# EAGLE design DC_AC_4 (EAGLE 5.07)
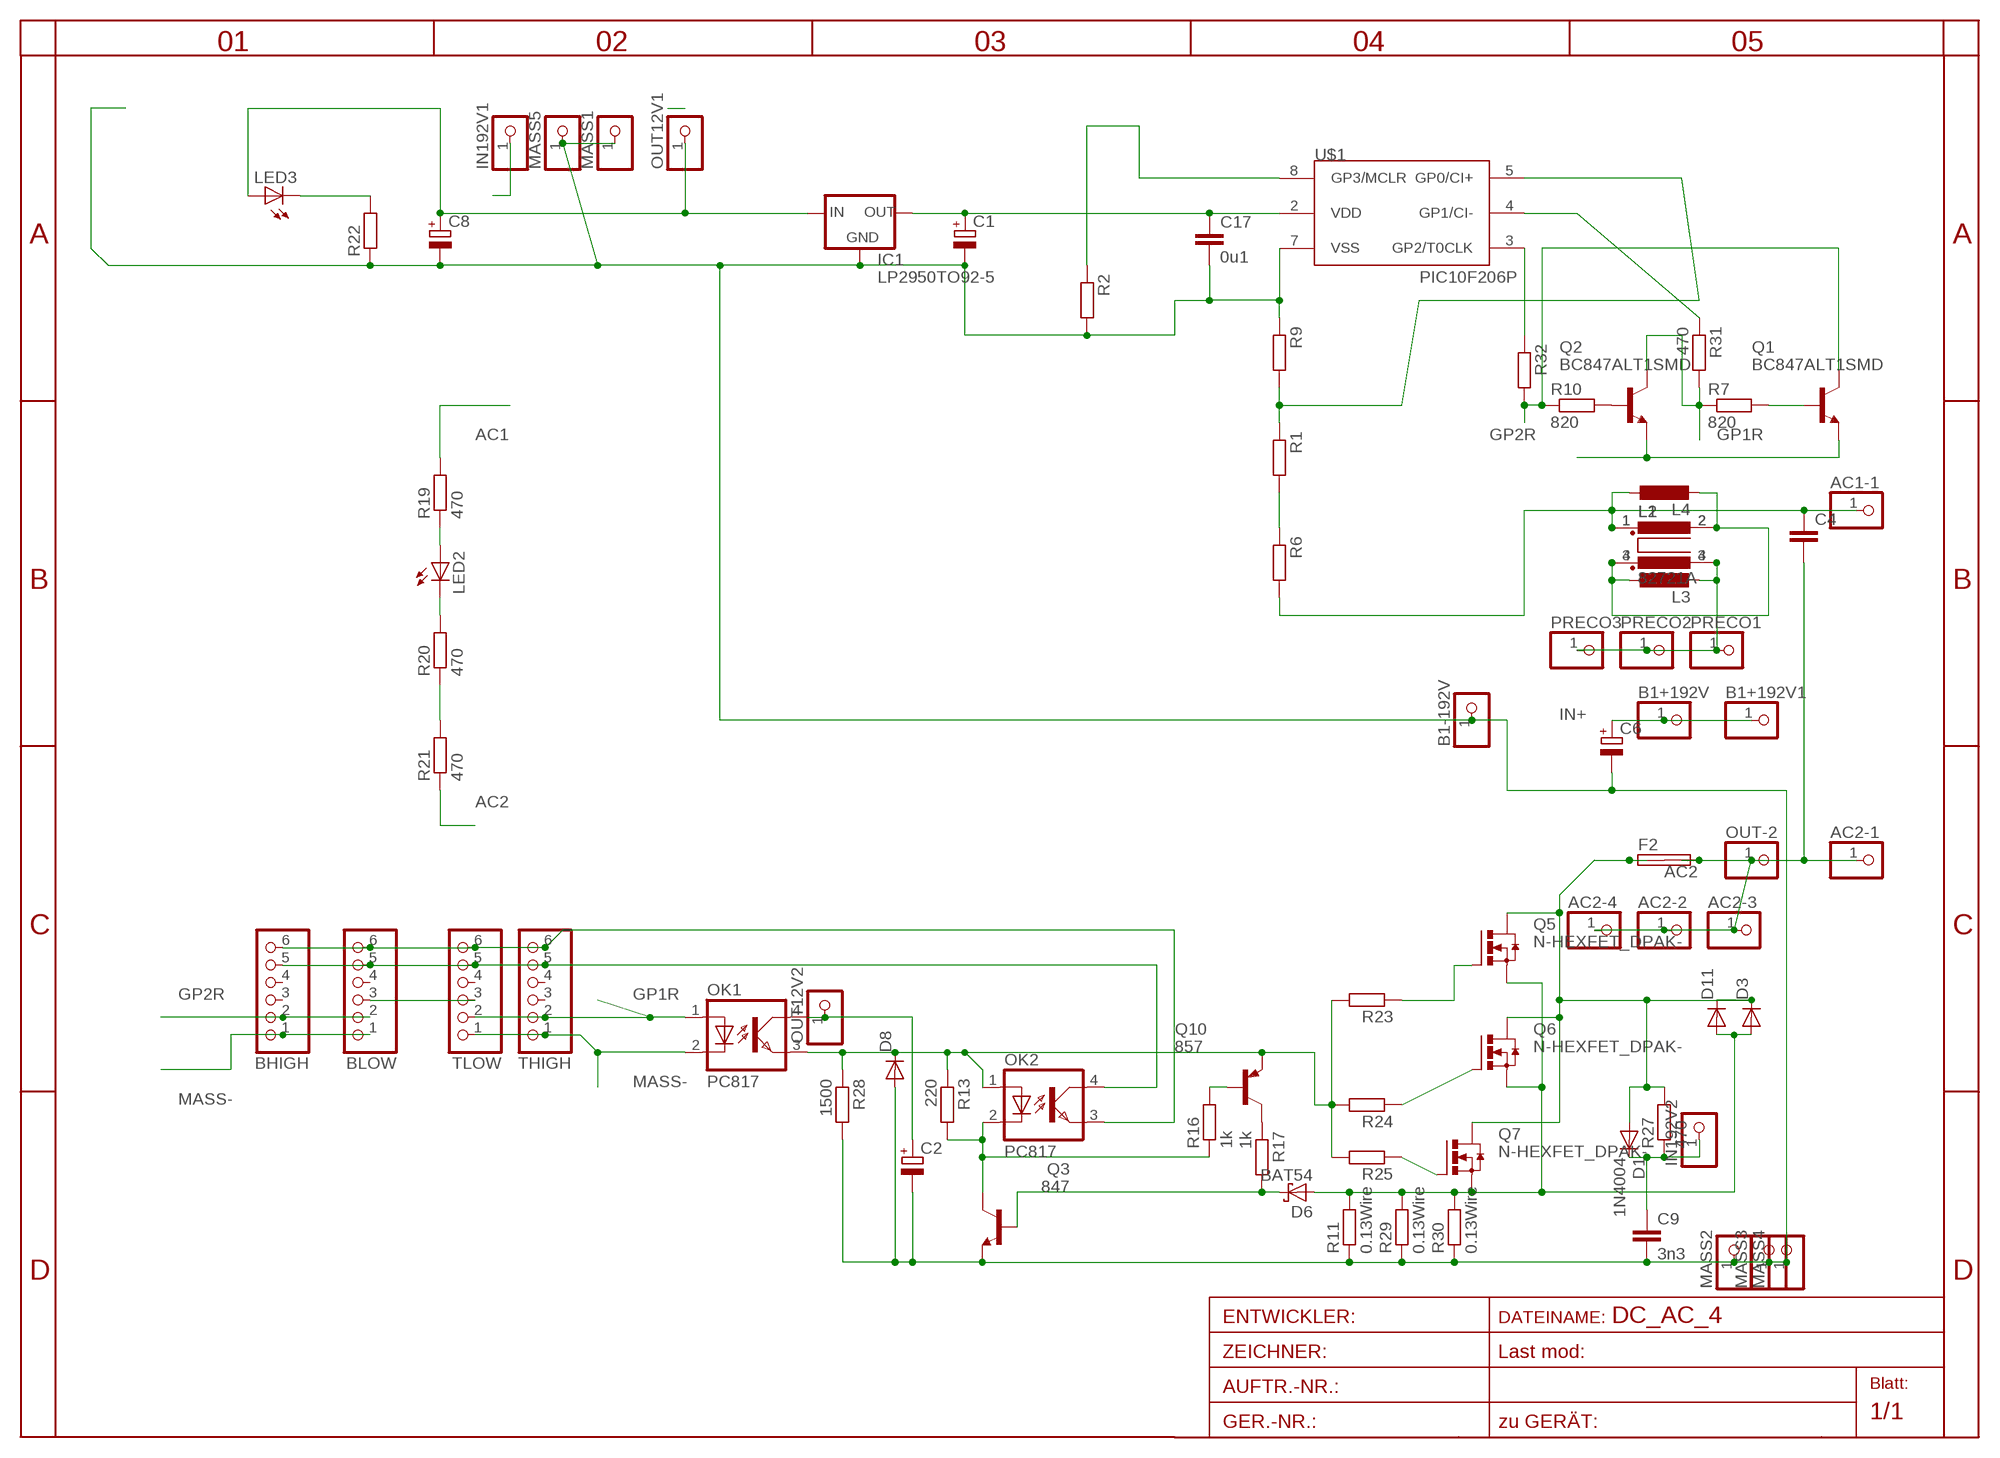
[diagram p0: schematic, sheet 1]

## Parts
AC1-1  PINHD-1X14.5MM  [1X4MM5]
AC2-1  PINHD-1X14.5MM  [1X4MM5]
AC2-2  PINHD-1X12MM3  [1X2MM3]
AC2-3  PINHD-1X12MM3  [1X2MM3]
AC2-4  PINHD-1X12MM3  [1X2MM3]
B1+192V  PINHD-1X12MM3  [1X2MM3]
B1+192V1  PINHD-1X12MM3  [1X2MM3]
B1-192V  PINHD-1X12MM3  [1X2MM3]
BHIGH  PINHD-1X6  [1X06BOX]
BLOW  PINHD-1X6  [1X06BOX]
C1  CPOL-EUE5-6  [E5-6]
C2  CPOL-EUE2.5-5  [E2,5-5]
C4  C-EU225-108X268  [C225-108X268]
C6  CPOL-EUE10-20  [EB20D]
C8  CPOL-EUE5-5  [E5-5]
C9  3n3  C-EU050-025X075  [C050-025X075]
C17  0u1  C-EUC1206  [C1206]
D1  1N4004  [DO41-10]
D3  DIODE-SMC  [SMC]
D6  BAT54  [SOT23]
D8  DIODE-MINIMELF  [MINIMELF]
D11  DIODE-SMC  [SMC]
F2  SHK20L7MM5  [7MM5]
IC1  LP2950TO92-5  [T092-5]
IN192V1  PINHD-1X11MM6  [1X1MM8]
IN192V2  PINHD-1X11MM0  [1X1MM0]
L1  R1405VB1  [B1]
L2  82721A  [82721A]
L3  L-EU2200-15.24  [2200-15.24]
L4  L-EU2200-15.24  [2200-15.24]
LED2  LED3MM  [LED3MM]
LED3  LEDCHIPLED_1206  [CHIPLED_1206]
MASS1  PINHD-1X11MM6  [1X1MM8]
MASS2  PINHD-1X11MM0  [1X1MM0]
MASS3  PINHD-1X11MM6  [1X1MM8]
MASS4  PINHD-1X11MM6  [1X1MM8]
MASS5  PINHD-1X11MM6  [1X1MM8]
OK1  PC817  [DIL04]
OK2  PC817  [DIL04]
OUT12V1  PINHD-1X11MM6  [1X1MM8]
OUT12V2  PINHD-1X11MM0  [1X1MM0]
OUT-2  PINHD-1X12MM3  [1X2MM3]
PRECO1  PINHD-1X12MM3  [1X2MM3]
PRECO2  PINHD-1X12MM3  [1X2MM3]
PRECO3  PINHD-1X12MM3  [1X2MM3]
Q1  BC847ALT1SMD  [SOT23]
Q2  BC847ALT1SMD  [SOT23]
Q3  847  BC846ALT1SMD  [SOT23]
Q5  N-HEXFET_DPAK-  [TO252]
Q6  N-HEXFET_DPAK-  [TO252]
Q7  N-HEXFET_DPAK-  [TO252]
Q10  857  BC857ALT1SMD  [SOT23-BEC]
R1  R-EU_0207/60  [0207/60]
R2  R-EU_R1206  [R1206]
R6  R-EU_0207/10  [0207/10]
R7  820  R-EU_R1206  [R1206]
R9  R-EU_R0805  [R0805]
R10  820  R-EU_R1206  [R1206]
R11  0.13Wire  R-EU_0204/5  [0204/5]
R13  220  R-EU_R1206  [R1206]
R16  1k  R-EU_R0805  [R0805]
R17  1k  R-EU_R0805  [R0805]
R19  470  R-EU_0204/5  [0204/5]
R20  470  R-EU_0204/2V  [0204V]
R21  470  R-EU_0204/5  [0204/5]
R22  R-EU_R1206  [R1206]
R23  R-EU_0207/15  [0207/15]
R24  R-EU_0207/10  [0207/10]
R25  R-EU_0207/12  [0207/12]
R27  470  R-EU_0207/10  [0207/10]
R28  1500  R-EU_R1206  [R1206]
R29  0.13Wire  R-EU_0204/5  [0204/5]
R30  0.13Wire  R-EU_0204/5  [0204/5]
R31  470  R-EU_R1206  [R1206]
R32  R-EU_R1206  [R1206]
THIGH  PINHD-1X6  [1X06BOX]
TLOW  PINHD-1X6  [1X06BOX]
U$1  PIC10F206P  [DIL8]

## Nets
AC1: AC1-1.1 C4.1 L1.1 L2.1 L4.1 R6.2 R19.2
AC2: AC2-1.1 AC2-2.1 AC2-3.1 AC2-4.1 C4.2 F2.2A F2.2B OUT-2.1 R21.1
BATT+: C8.+ IC1.3(IN) LED3.A OUT12V1.1
D1: D1.A D3.C D11.C F2.1A F2.1B Q5.3(D) Q6.3(D) Q7.3(D) R27.2
GP1R: OK1.1(A) Q2.3(C) R7.1 R31.2 THIGH.2 TLOW.2
GP2R: BHIGH.2 BLOW.2 Q1.3(C) R10.1 R32.2
GP3: BHIGH.6 BLOW.6 OK2.3(EMIT) R2.1 THIGH.6 TLOW.6 U$1.8(GP3/MCLR)
IN+: B1+192V1.1 B1+192V.1 C6.+ IN192V1.1
INN: L1.2 L1.3 L2.2 L2.4 L3.1 L4.2
MASS-: B1-192V.1 BHIGH.1 BLOW.1 C1.- C2.- C6.- C8.- C9.2 C17.2 D8.A IC1.2(GND) MASS1.1 MASS2.1 MASS3.1 MASS4.1 MASS5.1 OK1.2(C) Q1.2(E) Q2.2(E) Q3.2(E) R2.2 R9.1 R11.1 R22.1 R28.2 R29.1 R30.1 THIGH.1 TLOW.1 U$1.7(VSS)
N$1: R1.1 R9.2 U$1.5(GP0/CI+)
N$2: C2.+ OK1.4(COL) OUT12V2.1
N$3: R1.2 R6.1
N$4: Q2.1(B) R10.2
N$5: BLOW.3 TLOW.3
N$6: LED2.A R19.1
N$7: Q1.1(B) R7.2
N$9: LED2.K(C) R20.2
N$11: D6.3(C) Q3.1(B) R17.2
N$12: OK2.2(C) Q3.3(C) R13.2 R16.1
N$13: R20.1 R21.2
N$15: LED3.C R22.2
N$16: Q10.B R16.2
N$17: Q10.C R17.1
N$20: C9.1 D1.C IN192V2.1 R27.1
N$25: Q7.1(G) R25.1
N$26: Q6.1(G) R24.1
N$27: Q5.1(G) R23.1
N$39: R31.1 U$1.4(GP1/CI-)
N$43: R32.1 U$1.3(GP2/T0CLK)
PP1: D8.C OK1.3(EMIT) OK2.1(A) Q10.E R13.1 R23.2 R24.2 R25.2 R28.1
PRECOIL: L1.4 L2.3 L3.2 PRECO1.1 PRECO2.1 PRECO3.1
SRC1: D3.A D6.1(A) D11.A Q5.2(S) Q6.2(S) Q7.2(S) R11.2 R29.2 R30.2
VDD: BHIGH.5 BLOW.5 C1.+ C17.1 IC1.1(OUT) OK2.4(COL) THIGH.5 TLOW.5 U$1.2(VDD)
Unconnected: BHIGH.3 BHIGH.4 BLOW.4 THIGH.3 THIGH.4 TLOW.4

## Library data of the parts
AC1-1 AC2-1-AC2-4 B1+192V B1+192V1 B1-192V IN192V1 IN192V2 MASS1-MASS5 OUT12V1 OUT12V2 OUT-2 PRECO1-PRECO3 = pinhead:PINHD-1X1: PIN HEADER
BHIGH BLOW THIGH TLOW = pinhead:PINHD-1X6: PIN HEADER
C1 C2 C8 = rcl-2:CPOL-EU: POLARIZED CAPACITOR, European symbol
C4 = rcl:C-EU: CAPACITOR, European symbol
C6 = rcl:CPOL-EU: POLARIZED CAPACITOR, European symbol
C9 C17 = rcl-2:C-EU: CAPACITOR, European symbol
D1 = diode:1N4004: DIODE
D3 D8 D11 = diode:DIODE-: DIODE
D6 = diode:BAT54: Schottky Diodes
F2 = fuse:SHK20L: FUSE HOLDER 5 x 20 mm, SH contact, SHH1 Schukat, E1073 Buerklin
IC1 = v-reg:LP2950?*: Source: http://cache.national.com/ds/LP/LP2950.pdf
L1 = inductor-nkl:R1405V: Übertrager (verlustarm) bis typ. 400kHz Power transformer (low loss) up to typ. 400kHz
L2 = inductors:82721A: FILTER
L3 L4 = rcl:L-EU: INDUCTOR, European symbol
LED2 LED3 = led:LED: LED
OK1 OK2 = optocoupler:PC817: SHARP OPTO COUPLER
Q1 Q2 = transistor-npn:BC847*: NPN Transistor
Q3 = transistor-npn:BC846*: NPN Transistor
Q5-Q7 = transistor-power:N-HEXFET_?-*: HEXFET® Power MOSFET
Q10 = transistor-pnp:BC857*: PNP Transistror
R1 R2 R6 R7 R9-R11 R13 R16 R17 R19-R25 R27-R32 = rcl-2:R-EU_: RESISTOR, European symbol
U$1 = microchip-5:PIC10F2*: uPC nW 0,25/0,5k Program Flash memory Comparator

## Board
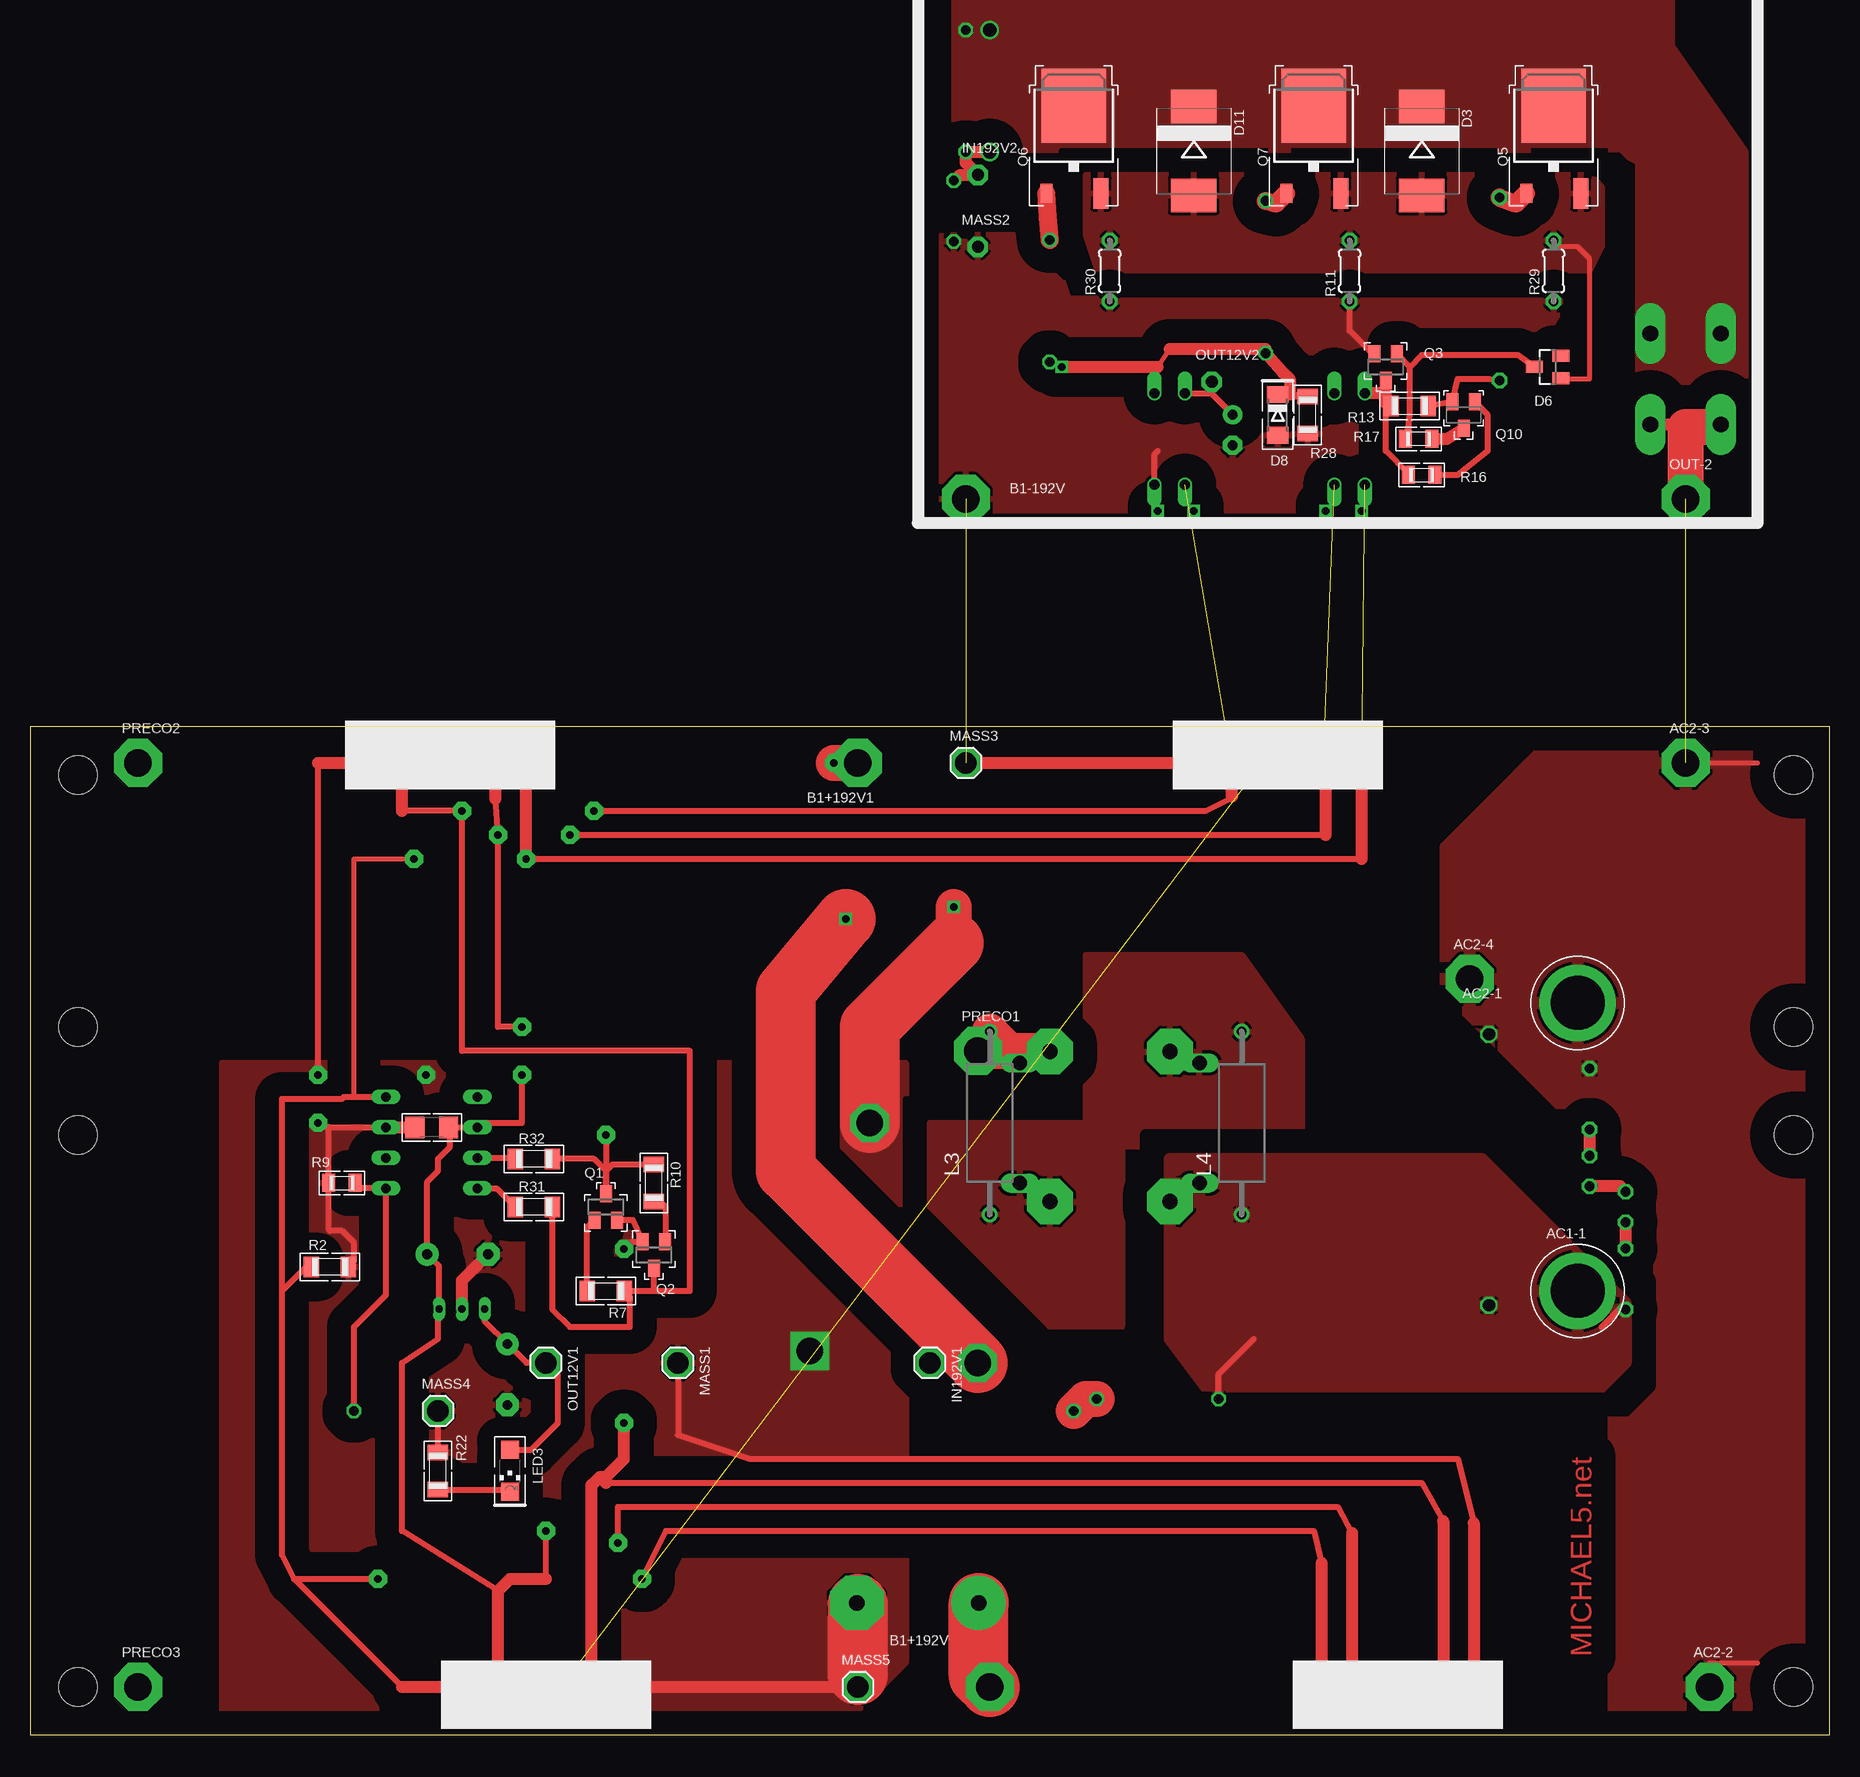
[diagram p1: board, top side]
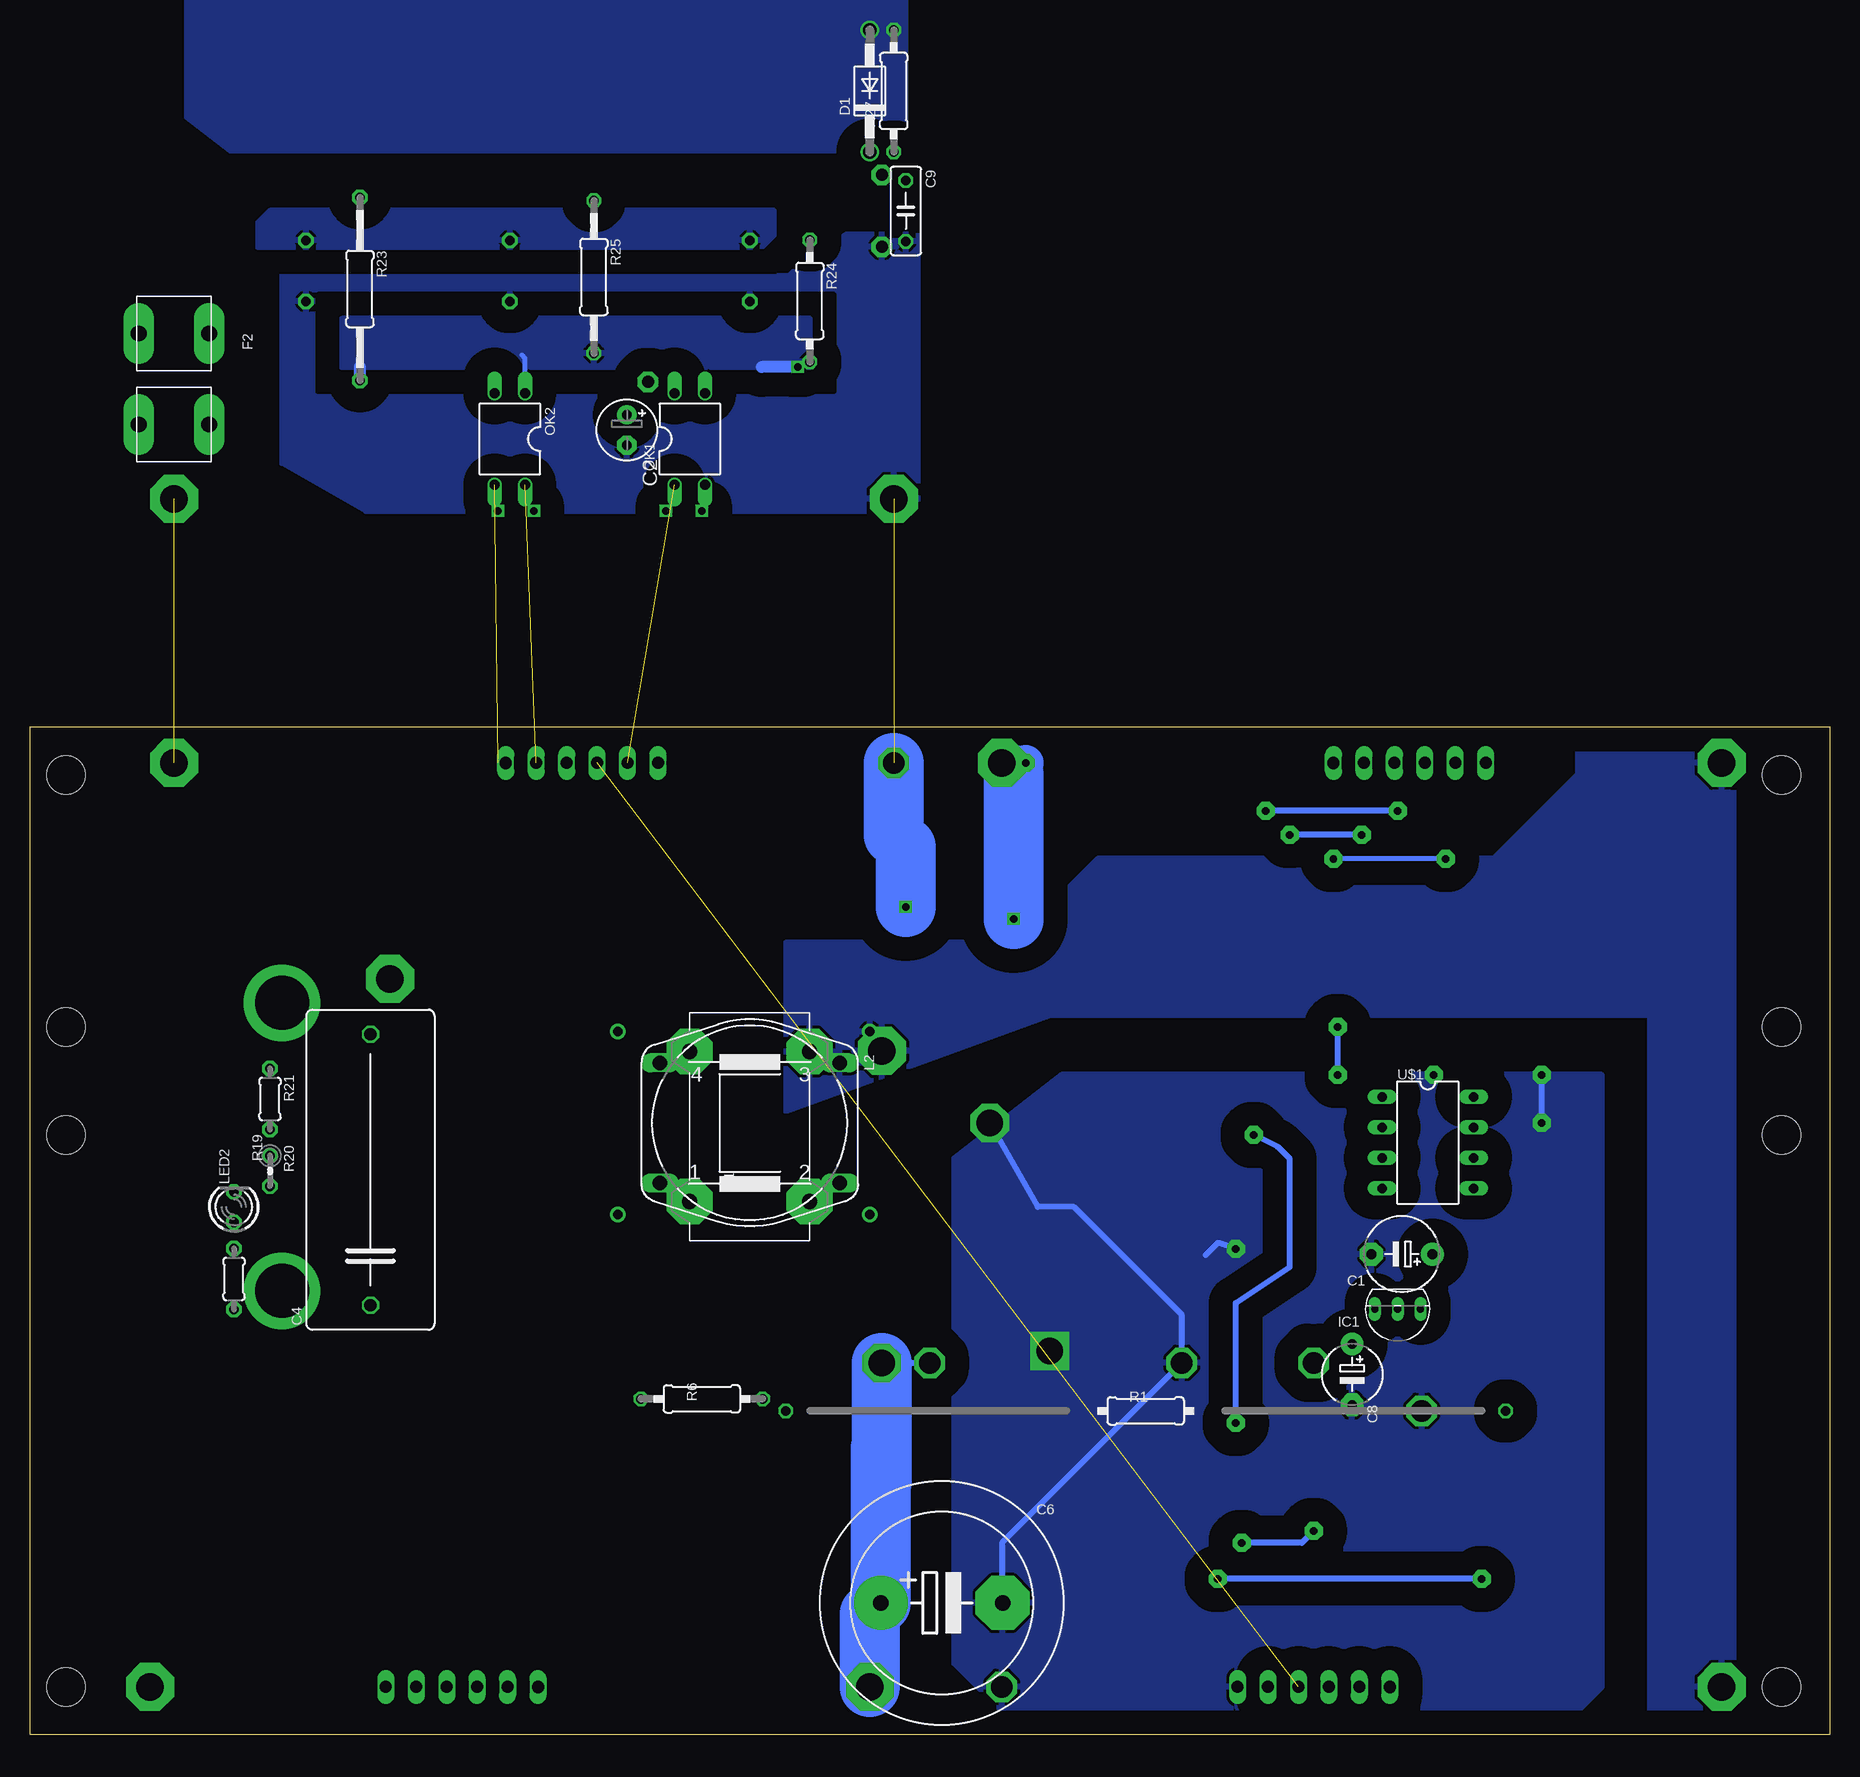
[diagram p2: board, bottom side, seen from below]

Size 150 x 84 mm. Coordinates in mm from the lower left corner, seen from the top.
Outline: 0,0 150,0 150,84 0,84 0,0
Copper layers (1*16): Top 0.035mm / dielectric 1.5mm / Bottom 0.035mm
Design rules "default *": minimum track width 12mil, minimum drill 24mil, track to track 8mil, track to pad 8mil, pad to pad 8mil, via to via 8mil, smd to smd 8mil, copper to edge 40mil, drill to drill 8mil, minimum pad ring 8mil, minimum via ring 8mil, stop-mask expansion 4mil, vias tented up to drill 0mil, thermal gap 10mil
Holes 3.2 mm at 4,80 4,4 4,59 4,50 147,80 147,4 147,59 147,50

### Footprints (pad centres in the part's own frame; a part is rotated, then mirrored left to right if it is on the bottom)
1X4MM5 = drill 4.5 pad 6.35 round: 1 0,0
1X2MM3 = drill 2.3 pad 4 octagon: 1 0,0
1X06BOX = drill 1 long: 1 -6.35,0; 2 -3.81,0; 3 -1.27,0; 4 1.27,0; 5 3.81,0 | drill 1.016 long: 6 6.35,0
E5-6 = drill 0.813 pad 1.905 round: + -2.54,0 | drill 0.813 pad 1.905 octagon: - 2.54,0
E2,5-5 = drill 0.813 pad 1.6 round: + -1.27,0 | drill 0.813 pad 1.6 octagon: - 1.27,0
C225-108X268 = drill 1.016 octagon: 1 -11.303,0; 2 11.303,0
EB20D = drill 1.3 pad 4.5 round: + -5.08,0 | drill 1.3 pad 4.5 octagon: - 5.08,0
E5-5 = drill 0.813 pad 1.905 round: + -2.54,0 | drill 0.813 pad 1.905 octagon: - 2.54,0
C050-025X075 = drill 0.813 octagon: 1 -2.54,0; 2 2.54,0
C1206 = smd 1.6 x 1.8: 1 -1.4,0; 2 1.4,0
DO41-10 = drill 1.118 round: A 5.08,0; C -5.08,0
SMC = smd 2.8 x 3.8: A 3.7,0; C -3.7,0
SOT23 = smd 1 x 1.4: 1 -0.95,-1.1; 2 0.95,-1.1; 3 0,1.1
MINIMELF = smd 1.4 x 1.8: A 1.7,0; C -1.7,0
7MM5 = drill 1.3 pad 2.54 long: 1A -3.8,2.94; 1B -3.8,-2.94; 2A 3.8,2.94; 2B 3.8,-2.94
T092-5 = drill 0.6 pad 0.813 long: 1 -1.905,0; 2 0,0; 3 1.905,0
1X1MM8 = drill 1.8 pad 2.54 octagon: 1 0,0
1X1MM0 = drill 1 pad 1.676 octagon: 1 0,0
B1 = drill 1.27 pad 3.81 octagon: 1 -6.25,5; 2 -6.25,-5; 3 6.25,5; 4 6.25,-5
82721A = drill 1.194 long: 1 7.493,5.004; 2 -7.493,5.004; 3 -7.493,-5.004; 4 7.493,-5.004
2200-15.24 = drill 0.8 pad 1.27 round: 1 -7.62,0; 2 7.62,0
LED3MM = drill 0.8 pad 1.27 octagon: A -1.27,0; K 1.27,0
CHIPLED_1206 = smd 1.5 x 1.5: A 0,-1.75; C 0,1.75
DIL04 = drill 0.813 offset: 1 -1.27,-3.81; 2 1.27,-3.81; 3 1.27,3.81; 4 -1.27,3.81
TO252 = smd 1 x 1.6: 1 -2.28,-3.53 | smd 1.27 x 2.54: 2 2.28,-3.53 | smd 5.4 x 6.2: 3 0,3.77
SOT23-BEC = smd 1 x 1.4: B -0.95,-1.1; C 0,1.1; E 0.95,-1.1
0207/60 = drill 0.813 octagon: 1 -30,0; 2 30,0
R1206 = smd 1.3 x 1.7: 1 -1.55,0; 2 1.55,0
0207/10 = drill 0.813 octagon: 1 -5.08,0; 2 5.08,0
R0805 = smd 1.1 x 1.5: 1 -1.1,0; 2 1.1,0
0204/5 = drill 0.8 pad 1.27 octagon: 1 -2.54,0; 2 2.54,0
0204V = drill 0.8 pad 1.27 octagon: 1 -1.27,0; 2 1.27,0
0207/15 = drill 0.8 pad 1.27 octagon: 1 -7.62,0; 2 7.62,0
0207/12 = drill 0.813 octagon: 1 -6.35,0; 2 6.35,0
DIL8 = drill 0.8 long: 1 -3.81,-3.81; 2 -1.27,-3.81; 3 1.27,-3.81; 4 3.81,-3.81; 5 3.81,3.81; 6 1.27,3.81; 7 -1.27,3.81; 8 -3.81,3.81

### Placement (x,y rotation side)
AC1-1  129,37 0 top
AC2-1  129,61 0 top
AC2-2  140,4 0 top
AC2-3  138,81 0 top
AC2-4  120,63 0 top
B1+192V  80,4 0 top
B1+192V1  69,81 180 top
B1-192V  not placed on the board
BHIGH  114,4 180 top
BLOW  43,4 180 top
C1  35.65,40.07 180 bottom
C2  100.25,108.75 270 bottom  (outside the outline)
C4  121.62,47.1 90 bottom
C6  74,11 0 bottom
C8  39.8,30.05 270 bottom
C9  77,127 270 bottom  (outside the outline)
C17  33.49,50.63 180 top
D1  80,137 90 bottom  (outside the outline)
D3  not placed on the board
D6  126.5,114 90 top  (outside the outline)
D8  104,110 270 top  (outside the outline)
D11  not placed on the board
F2  138,113 270 bottom  (outside the outline)
IC1  36,35.5 180 bottom
IN192V1  75,31 270 top
IN192V2  79,130 0 top  (outside the outline)
L1  90.03,50.7 90 bottom
L2  90,51 180 bottom
L3  80,51 90 top
L4  101,51 90 top
LED2  133,44 90 bottom
LED3  40,22 180 top
MASS1  54,31 270 top
MASS2  not placed on the board
MASS3  78,81 0 top
MASS4  34,27 0 top
MASS5  69,4 0 top
OK1  95,108 0 bottom  (outside the outline)
OK2  110,108 180 bottom  (outside the outline)
OUT12V1  43,31 270 top
OUT12V2  98.5,112.75 0 top  (outside the outline)
OUT-2  138,103 0 top  (outside the outline)
PRECO1  79,57 0 top
PRECO2  9,81 0 top
PRECO3  9,4 0 top
Q1  48,44 0 top
Q2  52,40 180 top
Q3  113,114 180 top  (outside the outline)
Q5  127,132 0 top  (outside the outline)
Q6  87,132 0 top  (outside the outline)
Q7  107,132 0 top  (outside the outline)
Q10  119.5,110 180 top  (outside the outline)
R1  57,27 180 bottom
R2  25,39 0 top
R6  94,28 180 bottom
R7  48,37 180 top
R9  26,46 0 top
R10  52,46 270 top
R11  110,122 90 top  (outside the outline)
R13  115,110.75 180 top  (outside the outline)
R16  116,105 0 top  (outside the outline)
R17  115.75,108 180 top  (outside the outline)
R19  133,38 270 bottom
R20  130,47 270 bottom
R21  130,53 270 bottom
R22  34,22 270 top
R23  122.5,120.5 270 bottom  (outside the outline)
R24  85,119.5 270 bottom  (outside the outline)
R25  103,121.5 270 bottom  (outside the outline)
R27  78,137 90 bottom  (outside the outline)
R28  106.5,110 270 top  (outside the outline)
R29  127,122 90 top  (outside the outline)
R30  not placed on the board
R31  42,44 0 top
R32  42,48 0 top
THIGH  35,81 0 top
TLOW  104,81 0 top
U$1  33.49,49.36 270 bottom

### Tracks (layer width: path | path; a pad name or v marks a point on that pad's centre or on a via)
AC1
  Top 0.5: R6.2 99.08,30.08 102,33 | R19.2 132.46,35.46 131,34
  pour Top (isolate 2): 95,48 121,48 133,36 133,31 131,29 98,29 95,33
AC2  (1 unrouted)
  Top 0.406: AC2-3.1 144,81 | 144,6 140,6 AC2-2.1
  Top 1: F2.2A F2.2B 140.74,109 140,109
  Top 3: OUT-2.1 138,109 140,109
  pour Top (isolate 2, rank 2): 130,83 146,83 148,81 148,5 144,1 133,1 132,2 132,48 118,62 118,74 126,82
BATT+
  Top 0.5: IC1.3 37.91,34.48 C8.+ 41.38,31 OUT12V1.1 44,30 44,26 41.75,23.75 LED3.A
D1
  pour Top (isolate 2, rank 2, no thermals): 77,148 137,148 136.89,146.25 136.89,140.82 143,132 143,111 134,111 134,131 132,132 77,132
  pour Bottom (isolate 2, rank 2, no thermals): 77,148 137,148 137,134.82 133.35,132 77,132
GP1R  (via drill 0.6 pad 1.5)  (1 unrouted)
  Top 0.5: 31,81 THIGH.2 | 52,37 R7.1 50,36.55 50,34 45,34 43.55,35.45 R31.2 | 52,37 55,37 55,57 36,57 v36,77 31,77 | 100.19,78.19 100,78 98,77 v47,77 | 52,37 Q2.3
  Top 1: 31,77 31,81 | 100.19,78.19 TLOW.2
  Bottom 0.5: v36,77 v47,77
GP2R  (via drill 0.6 pad 1.5)
  Top 0.5: 117.81,17.81 116,21 48,21 | R32.2 47,48 48,47 | 48,47 Q1.3 v48,50 | R10.1 48.55,47.55 48,47
  Top 1: 117.81,17.81 BHIGH.2 | BLOW.2 46.81,20.81 47.5,21.5 48,21.5 | v49.5,26 49.5,23 48,21.5 | 48,21.5 48,21
  Bottom 0.5: v49.5,26 49.5,36 45,39 45,48 46,49 v48,50
GP3  (via drill 0.6 pad 1.5)  (1 unrouted)
  Top 0.406: v32,73 27,73 27,53.17
  Top 0.5: 111,81 TLOW.6 | v41.35,73 111,73 | R2.1 23,39 21,37 | 21,37 21,15 22,13 | 22,13 31,4 | U$1.8 27,53.17 26.17,53.17 26,53 21,53 21,37 | 107.65,14.35 107,17 53,17 v51,13 | 22,13 v29,13
  Top 1: 111,73 111,81 | v41.35,73 THIGH.6 | 31,4 BLOW.6 | 107.65,14.35 BHIGH.6
  Bottom 0.406: v32,73 v41.35,73
  Bottom 0.5: v29,13 v51,13
IN+  (via drill 0.6, 0.6 pad 1.5, 2.2 pad 3)
  Top 3: v67,81 B1+192V1.1
  Top 5: v68,68 63,62 63,47 v79,31 | C6.+ 79.08,4.92 B1+192V.1
  Bottom 0.5: v79,31 IN192V1.1
  Bottom 3: 68,80 v67,81
  Bottom 5: B1+192V.1 80,10.08 | C6.+ 79.08,21 | 79.08,21 79.08,23.92 | v68,68 68,80 | v79,31 79,21.08 79.08,21
INN
  pour Top (isolate 2, rank 2): 88,65 101,65 106,58 106,49 91,49 91,34 85,34 75,44 75,51 88,51
MASS-  (via drill 0.6, 0.6 pad 1.5, 2.2 pad 3)  (1 unrouted)
  Top 0.5: OK1.2 93.73,106.73 94,107 | Q3.2 111.62,115.38 110,117 R11.1 | 29.68,51 U$1.7 25,50.63 | 120.35,17.65 119,23 60,23 54,25 MASS1.1 | 25,50.63 24.37,50.63 v24,51 | v24,55 24,81 | Q1.2 50.25,42.9 Q2.2 50.1,41.1 v49.5,40.5 | 25,50.63 24.9,50.53 R9.1 24.9,42.1 25,42 26,42 27,41 27,39.45 R2.2 | R22.1 MASS4.1
  Top 1: 24,81 THIGH.1 | 120.35,17.65 BHIGH.1 | IC1.2 36,37.88 C1.- | U$1.7 C17.2 | BLOW.1 MASS5.1 | MASS3.1 TLOW.1
  Top 3: 77,66 v77,69
  Top 5: v70,51 70,59 77,66 | 69,5 v69,10.92
  Bottom 0.5: v69,10.92 C6.- 68.92,16.08 MASS1.1 54,35 63,44 66,44 v70,51 | v24,51 v24,55 | v49.5,40.5 51,41 52,40
  Bottom 3: 77,74 78,75
  Bottom 5: v77,69 77,74 | 78,75 MASS3.1
  other vias: 65,32 33,55
  pour Top (isolate 2, rank 3): 76,125 82,125 86,121 129,121 119,105 117,102 76,102
  pour Bottom (isolate 2, rank 3): 76,125 82,125 86,122 129,122 129,106 122,102 76,102
  pour Bottom (isolate 2, rank 3): 19,55 64,55 73,48 73,6 69,2 21,2 19,4
  pour Top (isolate 2, rank 3): 16,56 73,56 73,6 69,2 16,1
N$1
  Top 0.5: R1.1 27,34 29.68,36.68 U$1.5 27.55,45.55 R9.2
N$2
  Top 0.5: OK1.4 98.46,111.81 98.5,111.77 | C2.+ 98.64,111.64 98.5,111.77 | 98.5,111.77 OUT12V2.1
N$3
  Top 3: R6.1 88,28 R1.2
N$4
  Top 0.5: R10.2 52.55,44.45 53,44 53,41.15 Q2.1
N$5  (1 unrouted)
N$6
  Top 1.016: R19.1 LED2.A
N$7
  Top 0.5: R7.2 46.45,42.3 Q1.1
N$9
  Top 1.016: R20.2 132.54,45.73 LED2.K
N$11
  Top 0.5: R17.2 114.9,108.9 115,110 115,113.96 | 115,113.96 Q3.1 | 115,113.96 116,115 124,115 D6.3
N$12
  Top 0.5: R16.1 114.9,105.1 113,107 113,111
  Top 1: 113,111.81 113,111 R13.2 | 113,111.81 OK2.2 | 113,111.81 Q3.3
N$13
  Top 1.016: R20.1 R21.2
N$15
  Top 0.5: R22.2 39.8,20.45 LED3.C
N$16
  Top 0.5: R16.2 119,105 121.5,107 121.5,110 Q10.B
N$17
  Top 1: R17.1 118.1,108 Q10.C
N$20
  Top 1: D1.C R27.1 78,131 IN192V2.1 77.54,130 C9.1
N$21  (via drill 0.6)
  other vias: 111,102
N$22  (via drill 0.6)
  other vias: 108,102
N$23  (via drill 0.6)
  other vias: 97,102
N$24  (via drill 0.6)
  other vias: 94,102
N$25
  Top 1.5: R25.1 103.87,127.62 Q7.1
N$26
  Top 1.5: Q6.1 84.85,126.47 R24.1
N$27
  Top 1.5: R23.1 123.87,127.62 Q5.1
N$39
  Top 0.5: U$1.4 38.9,45.55 R31.1
N$43
  Top 0.5: U$1.3 40.36,48.09 R32.1
PP1  (via drill 0.6)
  Top 0.406: 95,115.5 94,114 93.75,113.08 | 103,115.5 R25.2
  Top 0.5: 105.85,111.7 105,111.7 D8.C | 108.47,111.55 OK2.1 | R23.2 121.62,113 119,113 Q10.E 117.95,111 R13.1 | R28.1 105.45,111.55 105,112
  Top 1: 95,115.5 103,115.5 | R25.2 104.35,113.65 105,113 105,112 105,111.7 | v86,114 94,114 | 93.75,113.08 OK1.3
  Bottom 0.406: OK2.1 108.73,114.73 109,115 | R25.2 103,116
  Bottom 1: R23.2 122.5,114 | v86,114 89,114
  pour Bottom (isolate 2, rank 2): 85,118 124,118 124,114 85,114
PRECOIL
  Top 3: PRECO1.1 81.62,57 | 81.62,57 85,57 | 81.62,57 L3.2
  pour Bottom (isolate 2): 8,83 21,83 21,80 28,73 61,73 66,68 66,66 87,66 87,52 65,60 15,60 15,2 13,1 8,1
SRC1
  Top 0.406: R29.2 127.54,124 129,124 130,123 130,113 127.65,113 D6.1
  pour Top (isolate 2): 88,130 130,130 131,129 131,124 130,122 89,122 88,125
  pour Bottom (isolate 2): 88,127 130,127 131,126 131,124 89,124 88,125
VDD  (via drill 0.6 pad 1.5)  (1 unrouted)
  Top 0.5: THIGH.5 39,81 | v41,55 41,51 37.3,51 U$1.2 C17.1 35,50.52 35,49 34,48 34,47 33.11,46.11 C1.+ 34.09,39.09 IC1.1 34,35.41 34,33 31,31 31,17 39,12 | 108,81 TLOW.5 | v45,75 108,75 | 38.81,78 v39,75 39,59 v41,59 | BLOW.5 39.19,5.81 | 110.19,16.81 109,19 49,19 v49,16 | 43,13 v43,17
  Top 1: 108,75 108,81 | 38.81,78 THIGH.5 | 110.19,16.81 BHIGH.5
  Top 1.016: 43,13 40,13 39,12 39,4.19 BLOW.5
  Bottom 0.5: v41,55 v41,59 | v39,75 v45,75 | v49,16 44,16 v43,17

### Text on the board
Top: MICHAEL5.net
